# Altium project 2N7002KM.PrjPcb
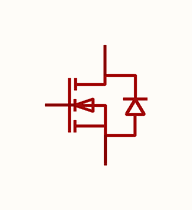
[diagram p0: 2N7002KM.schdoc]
1 sheet, 1 parts. Net scope: global (net labels, ports and power ports of the same name join across sheets).

## Sheet 2N7002KM.schdoc
size 127 x 101 mm

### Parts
Q?  2n7002km  [SOT-723_L1.2-W0.8-P0.40-LS1.2-BR]  (value not drawn)

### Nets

Not connected (* = marked no-connect by the designer): Q? 1(G) 2(S) 3(D)

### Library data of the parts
Q? = 2n7002km: 数量:1个N沟道;漏源电压(Vdss):60V;连续漏极电流(Id):200mA;导通电阻(RDS(on)):1.6Ω@10V；1.7Ω@4.5V;耗散功率(Pd):156mW;阈值电压(Vgs(th)):2V;; Manufacturer: MSKSEMI(美森科); AddInBom: yes; ModelId: abccde1e67074d7481274a37cf5c97f0; ModelName: SOT-723-3P_L1.2-W0.8-H0.6-LS1.2-P0.40; ModelTransform: 47.244,47.244,0,180,0,0,0,0,0; Number: 1个N沟道; Drain to Source Voltage: 60V; Current - Continuous Drain(Id): 200mA; Pd - Power Dissipation: 156mW; Gate Threshold Voltage (Vgs(th)): 2V; Gate Charge(Qg): 2nC@10V; Input Capacitance(Ciss): 25pF; Reverse Transfer Capacitance (Crss@Vds): 6.8pF; Output Capacitance(Coss): 15pF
